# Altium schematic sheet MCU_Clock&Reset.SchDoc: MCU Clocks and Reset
size A4; Date: Not used; ApprovedBy: Not used; CheckedBy: Not used; Author: Not used; CompanyName: STMicroelectronics; DrawnBy: Not used; Engineer: Not used; Organization: Not used; Address1: Not used; Address2: Not used; Address3: Not used; Address4: Not used; DocumentNumber: Not used; Revision: Not used; SheetNumber: 4; SheetTotal: 23
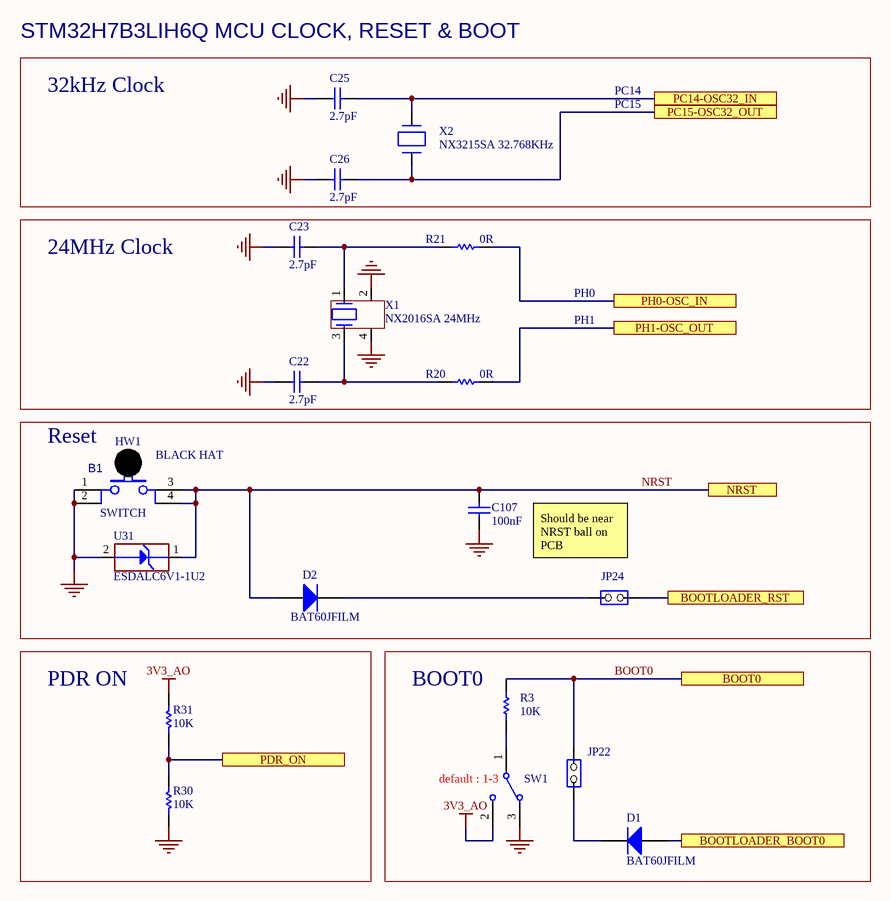
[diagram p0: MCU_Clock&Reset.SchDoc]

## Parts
B1  value SWITCH  [SWI_WEALTHMETAL_TD-0341_4P_BLACK]  (hidden comment: SW-PUSH-CMS)
C22  value 2.7pF  [C0603]  (hidden comment: Capacitor)
C23  value 2.7pF  [C0603]  (hidden comment: Capacitor)
C25  value 2.7pF  [C0603]  (hidden comment: Capacitor)
C26  value 2.7pF  [C0603]  (hidden comment: Capacitor)
C107  value 100nF  [C0402]  (hidden comment: Capacitor)
D1  BAT60JFILM  [DIO_SOD323]
D2  BAT60JFILM  [DIO_SOD323]
HW1  value BLACK HAT  (hidden comment: BUTTON_HAT_BLACK)  (mechanical)
JP22  Jumper_Header 2x1  [CON_SAMTEC_TSW-102-07-G-S]  (value not drawn)
JP24  Jumper_Header 2x1  [CON_SAMTEC_TSW-102-07-G-S]  (value not drawn)
R3  value 10K  [R0402]  (hidden comment: Resistor)
R20  value 0R  [R0402]  (hidden comment: Resistor)
R21  value 0R  [R0402]  (hidden comment: Resistor)
R30  value 10K  [R0402]  (hidden comment: Resistor)
R31  value 10K  [R0402]  (hidden comment: Resistor)
SW1  SW_MECA_1K2  [SWI_EAO_09-03290-01_EXTENDED_STRAIGHT_BLACK]  (value not drawn)
U31  value ESDALC6V1-1U2  [ESD_ST0201]  (hidden comment: ESD-TRANSIL)
X1  value NX2016SA 24MHz  [CRY_NX2016SA_4P]  (hidden comment: XTAL_4_PINS)
X2  value NX3215SA 32.768KHz  [CRY_NX3215SA_2P]  (hidden comment: XTAL_2_PINS)

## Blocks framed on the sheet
24MHz Clock: C22 C23 R20 R21 X1
Reset: B1 C107 D2 HW1 JP24 U31
PDR ON: R30 R31
BOOT0: D1 JP22 R3 SW1

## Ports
BOOT0, BOOTLOADER_BOOT0, BOOTLOADER_RST, NRST, PC14-OSC32_IN, PC15-OSC32_OUT, PDR_ON, PH0-OSC_IN, PH1-OSC_OUT

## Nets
3V3_AO: R31.1 SW1.2
GND: B1.1 B1.2 C22.1 C23.1 C25.1 C26.1 C107.1 R30.2 SW1.3 U31.2(GND) X1.2 X1.4
BOOT0: JP22.2(NO) R3.1 ; port BOOT0
BOOTLOADER_BOOT0: D1.1(A) ; port BOOTLOADER_BOOT0
BOOTLOADER_RST: JP24.2(NO) ; port BOOTLOADER_RST
NRST: B1.3 B1.4 C107.2 D2.1(A) U31.1(IO1) ; port NRST
PC14-OSC32_IN: C25.2 X2.2(X2) ; port PC14-OSC32_IN
PC15-OSC32_OUT: C26.2 X2.1(X1) ; port PC15-OSC32_OUT
PDR_ON: R30.1 R31.2 ; port PDR_ON
PH0-OSC_IN: R21.2 ; port PH0-OSC_IN
PH1-OSC_OUT: R20.2 ; port PH1-OSC_OUT
NetC22_2: C22.2 R20.1 X1.3
NetC23_2: C23.2 R21.1 X1.1
NetD1_2: D1.2(K) JP22.1(COMMON)
NetD2_2: D2.2(K) JP24.1(COMMON)
NetR3_2: R3.2 SW1.1

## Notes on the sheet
- STM32H7B3LIH6Q MCU CLOCK, RESET & BOOT
- 32kHz Clock
- PC14
- PC15
- PH0
- PH1
- Should be near NRST ball on PCB
- (near SW1) default : 1-3

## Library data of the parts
B1 = MCD-00001: Non-Open Push-Button 0.1A 24V BLACK; Manufacturer_Part_Number: TD-0341; Manufacturer: WEALTHMETAL; Part_Type: Misc; Provided_By: SUBCO
C22 C23 C25 C26 = MCD-01726: Capacitor, MLCC, 2.7pF, 50V, NPO, -+0.25pF 0603; Manufacturer_Part_Number: CC0603CRNPO9BN2R7; Manufacturer: YAGEO; Provided_By: SUBCO
C107 = MCD-00006: Capacitor, MLCC, 100nF, 16V, X7R, 10%, 0402, T=0.5mm; Manufacturer_Part_Number: CC0402KRX7R7BB104; Manufacturer: YAGEO; Alternate_Manufacturer_Part_Number: GCM155R71C104KA55D; Alternate_Manufacturer: MURATA; Provided_By: SUBCO; ECCN_US: EAR99; ECCN_EU: NEC
D1 D2 = MCD-00034: Manufacturer: STMICROELECTRONICS; Part_Type: Diode; BMS_Part_Number: 9151097; Provided_By: SUBCO with ST control; ECCN_US: EAR99; ECCN_EU: NEC
HW1 = MCD-00635: Black Hat for switch TD0341X-G01-BLA; Part_Type: Mechanical; Manufacturer_Part_Number: 988.16.09.3.00003_SH-517; Manufacturer: JIUBABA; Provided_By: SUBCO
JP22 JP24 = MCD-00045: Header, 2x1, 2,54mm, VR, TH, Height 5.84mm/2.54mm; Manufacturer_Part_Number: TSW-102-07-x-S; Manufacturer: SAMTEC; Part_Type: Connector; Alternate_Manufacturer_Part_Number: 313102S111116;313102S111116; Alternate_Manufacturer: JIUBABA; LIANYI; Value: Shunt not fitted; Provided_By: SUBCO
R3 R30 R31 = MCD-00053: Resistor,10K,0402,1%,1/16W; Manufacturer_Part_Number: RC0402FR-0710KL; Manufacturer: YAGEO; Provided_By: SUBCO; ECCN_US: EAR99; ECCN_EU: NEC
R20 R21 = MCD-00052: Resistor,0R,0402,5%,1/16W; Manufacturer_Part_Number: RC0402JR-070RL; Manufacturer: YAGEO; Provided_By: SUBCO; ECCN_US: EAR99; ECCN_EU: NEC
SW1 = MCD-00566: Mechanical Slide Switches 1K2 BLK ACT GOLD STRT MNT; Part_Type: Misc; Manufacturer_Part_Number: 09.03290.01; Manufacturer: EAO; Value: Mechanical Slide Switch 1K2; Provided_By: SUBCO
U31 = MCD-00170: ESD protection 6V1; Part_Type: Diode; Manufacturer: STMICROELECTRONICS; BMS_Part_Number: 9151132; Provided_By: SUBCO with ST control; ECCN_US: EAR99; ECCN_EU: NEC
X1 = MCD-01036: Crystal 24MHz, 6pF, +-20ppm, 80ohms max, SMD; Part_Type: Crystal_Osc; Manufacturer_Part_Number: NX2016SA 24MHz EXS00A-CS10820; Manufacturer: NDK; BMS_Part_Number: 9157045; Provided_By: SUBCO; ECCN_US: EAR99; ECCN_EU: NEC
X2 = MCD-00091: Crystal 32.768kHz, 6pF, +-20ppm, 50Kohms max, SMD; Part_Type: Crystal_Osc; Manufacturer_Part_Number: NX3215SA 32.768KHz EXS00A-MU00525; Manufacturer: NDK; BMS_Part_Number: 9157034; Provided_By: SUBCO; ECCN_US: EAR99; ECCN_EU: NEC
